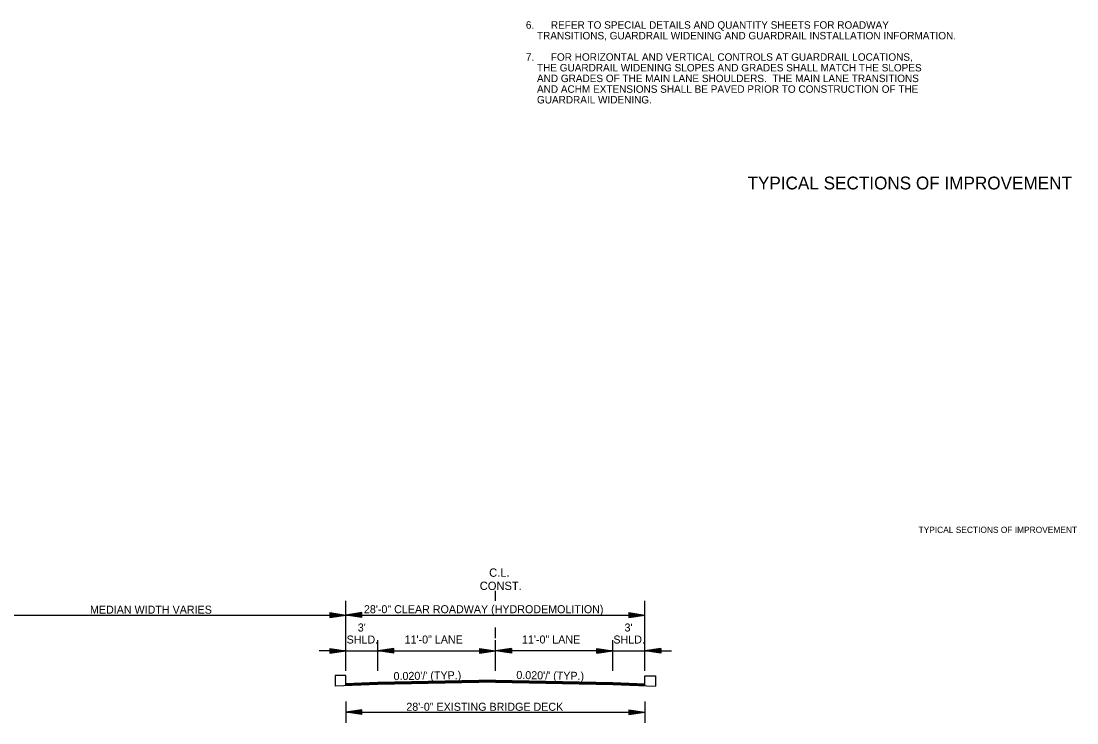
# Model space of a CAD drawing. Extents: x 542112 to 1930787, y -1968972 to 596640.
# Drawn here: x 544766 to 545755, y -1960540 to -1959883 of the extents above; entities that cross this region are included whole.
import ezdxf

# ---------------------------------------------------------------- set-up
doc = ezdxf.new("R2010")
doc.units = 0
for name, color, linetype in [('R_Border', 7, 'Continuous'), ('R_Border Notes', 7, 'Continuous'), ('R_Border Prem', 7, 'Continuous'), ('R_Draft', 7, 'Continuous')]:
    doc.layers.add(name, color=color, linetype=linetype)

msp = doc.modelspace()

# ---------------------------------------------------------------- linework, layer by layer
at = {"layer": 'R_Border'}
for p, q in [((545070.27, -1960495.83), (545060.1, -1960495.83)), ((545060.1, -1960495.83), (545060.1, -1960505.84)), ((545070.27, -1960505.44), (545070.27, -1960495.83)), ((545350.27, -1960496.03), (545360.44, -1960496.03)), ((545350.27, -1960505.44), (545350.27, -1960496.03)), ((545360.44, -1960496.03), (545360.44, -1960505.84))]:
    msp.add_line(p, q, dxfattribs=at)
at = {"layer": 'R_Draft'}
for p, q in [((545210.27, -1960425.81), (545210.27, -1960416.51)), ((545070.27, -1960491.59), (545070.27, -1960425.86)), ((545350.27, -1960491.59), (545350.27, -1960425.86)), ((544700.26, -1960439.22), (545070.27, -1960439.22)), ((545055.27, -1960436.97), (545070.27, -1960439.22)), ((545055.27, -1960436.97), (545055.27, -1960441.47)), ((545055.27, -1960437.35), (545067.76, -1960439.22)), ((545055.27, -1960437.73), (545065.18, -1960439.22)), ((545055.27, -1960438.11), (545062.69, -1960439.22)), ((545055.27, -1960438.5), (545060.14, -1960439.22)), ((545055.27, -1960438.87), (545057.64, -1960439.22)), ((545055.27, -1960441.47), (545070.27, -1960439.22)), ((545055.27, -1960439.96), (545060.14, -1960439.22)), ((545055.27, -1960440.72), (545065.18, -1960439.22)), ((545055.27, -1960441.1), (545067.76, -1960439.22)), ((545055.27, -1960440.34), (545062.69, -1960439.22)), ((545055.27, -1960439.58), (545057.64, -1960439.22)), ((545085.27, -1960436.97), (545070.27, -1960439.22)), ((545070.27, -1960439.22), (545350.27, -1960439.22)), ((545085.27, -1960441.47), (545070.27, -1960439.22)), ((545085.27, -1960437.35), (545072.77, -1960439.22)), ((545085.27, -1960441.1), (545072.77, -1960439.22)), ((545085.27, -1960437.73), (545075.35, -1960439.22)), ((545085.27, -1960440.72), (545075.35, -1960439.22)), ((545085.27, -1960438.11), (545077.85, -1960439.22)), ((545085.27, -1960440.34), (545077.85, -1960439.22)), ((545085.27, -1960438.49), (545080.39, -1960439.22)), ((545085.27, -1960439.95), (545080.39, -1960439.22)), ((545085.27, -1960438.87), (545082.9, -1960439.22)), ((545085.27, -1960439.58), (545082.9, -1960439.22)), ((545085.27, -1960441.47), (545085.27, -1960436.97)), ((545335.27, -1960436.97), (545350.27, -1960439.22)), ((545335.27, -1960436.97), (545335.27, -1960441.47)), ((545335.27, -1960437.35), (545347.76, -1960439.22)), ((545335.27, -1960437.73), (545345.18, -1960439.22)), ((545335.27, -1960438.11), (545342.69, -1960439.22)), ((545335.27, -1960438.5), (545340.14, -1960439.22)), ((545335.27, -1960438.87), (545337.64, -1960439.22)), ((545335.27, -1960441.47), (545350.27, -1960439.22)), ((545335.27, -1960439.96), (545340.14, -1960439.22)), ((545335.27, -1960440.72), (545345.18, -1960439.22)), ((545335.27, -1960441.1), (545347.76, -1960439.22)), ((545335.27, -1960440.34), (545342.69, -1960439.22)), ((545335.27, -1960439.58), (545337.64, -1960439.22)), ((545210.27, -1960460.75), (545210.27, -1960450.88)), ((545100.27, -1960491.59), (545100.27, -1960462.87)), ((545210.27, -1960491.42), (545210.27, -1960462.87)), ((545320.27, -1960491.59), (545320.27, -1960462.87)), ((545350.27, -1960491.59), (545350.27, -1960462.87)), ((545070.27, -1960472.76), (545045.27, -1960472.76)), ((545055.27, -1960470.51), (545070.27, -1960472.76)), ((545055.27, -1960470.51), (545055.27, -1960475.01)), ((545055.27, -1960470.89), (545067.76, -1960472.76)), ((545055.27, -1960471.27), (545065.18, -1960472.76)), ((545055.27, -1960471.64), (545062.69, -1960472.76)), ((545055.27, -1960472.03), (545060.14, -1960472.76)), ((545055.27, -1960472.41), (545057.64, -1960472.76)), ((545055.27, -1960475.01), (545070.27, -1960472.76)), ((545055.27, -1960473.5), (545060.14, -1960472.76)), ((545055.27, -1960474.25), (545065.18, -1960472.76)), ((545055.27, -1960474.64), (545067.76, -1960472.76)), ((545055.27, -1960473.88), (545062.69, -1960472.76)), ((545055.27, -1960473.11), (545057.64, -1960472.76)), ((545070.27, -1960472.76), (545100.27, -1960472.76)), ((545115.27, -1960470.51), (545100.27, -1960472.76)), ((545115.27, -1960475.01), (545100.27, -1960472.76)), ((545100.27, -1960472.76), (545210.27, -1960472.76)), ((545115.27, -1960470.89), (545102.77, -1960472.76)), ((545115.27, -1960474.64), (545102.77, -1960472.76)), ((545115.27, -1960471.27), (545105.35, -1960472.76)), ((545115.27, -1960474.25), (545105.35, -1960472.76)), ((545115.27, -1960471.64), (545107.85, -1960472.76)), ((545115.27, -1960473.88), (545107.85, -1960472.76)), ((545115.27, -1960472.03), (545110.39, -1960472.76)), ((545115.27, -1960473.49), (545110.39, -1960472.76)), ((545115.27, -1960472.41), (545112.9, -1960472.76)), ((545115.27, -1960473.11), (545112.9, -1960472.76)), ((545115.27, -1960475.01), (545115.27, -1960470.51)), ((545195.27, -1960470.51), (545210.27, -1960472.76)), ((545195.27, -1960470.51), (545195.27, -1960475.01)), ((545195.27, -1960470.89), (545207.76, -1960472.76)), ((545195.27, -1960471.27), (545205.18, -1960472.76)), ((545195.27, -1960471.64), (545202.69, -1960472.76)), ((545195.27, -1960472.03), (545200.14, -1960472.76)), ((545195.27, -1960472.41), (545197.64, -1960472.76)), ((545195.27, -1960475.01), (545210.27, -1960472.76)), ((545195.27, -1960473.5), (545200.14, -1960472.76)), ((545195.27, -1960474.25), (545205.18, -1960472.76)), ((545195.27, -1960474.64), (545207.76, -1960472.76)), ((545195.27, -1960473.88), (545202.69, -1960472.76)), ((545195.27, -1960473.11), (545197.64, -1960472.76)), ((545225.27, -1960470.51), (545210.27, -1960472.76)), ((545320.27, -1960472.76), (545210.27, -1960472.76)), ((545225.27, -1960475.01), (545210.27, -1960472.76)), ((545225.27, -1960470.89), (545212.77, -1960472.76)), ((545225.27, -1960474.64), (545212.77, -1960472.76)), ((545225.27, -1960471.27), (545215.35, -1960472.76)), ((545225.27, -1960474.25), (545215.35, -1960472.76)), ((545225.27, -1960471.64), (545217.85, -1960472.76)), ((545225.27, -1960473.88), (545217.85, -1960472.76)), ((545225.27, -1960472.03), (545220.39, -1960472.76)), ((545225.27, -1960473.5), (545220.39, -1960472.76)), ((545225.27, -1960472.41), (545222.9, -1960472.76)), ((545225.27, -1960473.11), (545222.9, -1960472.76)), ((545225.27, -1960470.51), (545225.27, -1960475.01)), ((545305.27, -1960470.51), (545320.27, -1960472.76)), ((545305.27, -1960475.01), (545305.27, -1960470.51)), ((545305.27, -1960470.89), (545317.76, -1960472.76)), ((545305.27, -1960471.27), (545315.18, -1960472.76)), ((545305.27, -1960471.64), (545312.69, -1960472.76)), ((545305.27, -1960472.03), (545310.14, -1960472.76)), ((545305.27, -1960472.41), (545307.64, -1960472.76)), ((545305.27, -1960475.01), (545320.27, -1960472.76)), ((545305.27, -1960473.49), (545310.14, -1960472.76)), ((545305.27, -1960474.25), (545315.18, -1960472.76)), ((545305.27, -1960474.64), (545317.76, -1960472.76)), ((545305.27, -1960473.88), (545312.69, -1960472.76)), ((545305.27, -1960473.11), (545307.64, -1960472.76)), ((545320.27, -1960472.76), (545350.27, -1960472.76)), ((545365.27, -1960470.51), (545350.27, -1960472.76)), ((545365.27, -1960475.01), (545350.27, -1960472.76)), ((545350.27, -1960472.76), (545375.27, -1960472.76)), ((545365.27, -1960470.89), (545352.77, -1960472.76)), ((545365.27, -1960474.64), (545352.77, -1960472.76)), ((545365.27, -1960471.27), (545355.35, -1960472.76)), ((545365.27, -1960474.25), (545355.35, -1960472.76)), ((545365.27, -1960471.64), (545357.85, -1960472.76)), ((545365.27, -1960473.88), (545357.85, -1960472.76)), ((545365.27, -1960472.03), (545360.39, -1960472.76)), ((545365.27, -1960473.5), (545360.39, -1960472.76)), ((545365.27, -1960472.41), (545362.9, -1960472.76)), ((545365.27, -1960473.11), (545362.9, -1960472.76)), ((545365.27, -1960470.51), (545365.27, -1960475.01)), ((545100.27, -1960504.24), (545060.1, -1960505.84)), ((545100.27, -1960502.57), (545070.27, -1960503.77)), ((545100.27, -1960502.87), (545070.27, -1960504.07)), ((545100.27, -1960503.17), (545070.27, -1960504.37)), ((545100.27, -1960503.47), (545070.27, -1960504.67)), ((545100.27, -1960503.77), (545070.27, -1960504.97)), ((545100.27, -1960504.07), (545070.27, -1960505.27)), ((545210.27, -1960500.37), (545100.27, -1960502.57)), ((545210.27, -1960500.67), (545100.27, -1960502.87)), ((545210.28, -1960500.97), (545100.27, -1960503.17)), ((545210.29, -1960501.27), (545100.27, -1960503.47)), ((545210.29, -1960501.57), (545100.27, -1960503.77)), ((545210.3, -1960501.87), (545100.27, -1960504.07)), ((545210.3, -1960502.04), (545100.27, -1960504.24)), ((545210.23, -1960502.04), (545320.27, -1960504.24)), ((545210.24, -1960501.57), (545320.27, -1960503.77)), ((545210.24, -1960501.87), (545320.27, -1960504.07)), ((545210.25, -1960501.27), (545320.27, -1960503.47)), ((545210.26, -1960500.67), (545320.27, -1960502.87)), ((545210.26, -1960500.97), (545320.27, -1960503.17)), ((545210.27, -1960500.37), (545320.27, -1960502.57)), ((545320.27, -1960502.57), (545350.27, -1960503.77)), ((545320.27, -1960502.87), (545350.27, -1960504.07)), ((545320.27, -1960503.17), (545350.27, -1960504.37)), ((545320.27, -1960503.47), (545350.27, -1960504.67)), ((545320.27, -1960503.77), (545350.27, -1960504.97)), ((545320.27, -1960504.07), (545350.27, -1960505.27)), ((545320.27, -1960504.24), (545360.44, -1960505.84)), ((545070.27, -1960520.23), (545070.27, -1960540.23)), ((545350.27, -1960520.23), (545350.27, -1960540.23)), ((545085.27, -1960527.98), (545070.27, -1960530.23)), ((545070.27, -1960530.23), (545350.27, -1960530.23)), ((545085.27, -1960532.48), (545070.27, -1960530.23)), ((545085.27, -1960528.35), (545072.77, -1960530.23)), ((545085.27, -1960532.1), (545072.77, -1960530.23)), ((545085.27, -1960528.73), (545075.35, -1960530.23)), ((545085.27, -1960531.72), (545075.35, -1960530.23)), ((545085.27, -1960529.11), (545077.85, -1960530.23)), ((545085.27, -1960531.34), (545077.85, -1960530.23)), ((545085.27, -1960529.49), (545080.39, -1960530.23)), ((545085.27, -1960530.95), (545080.39, -1960530.23)), ((545085.27, -1960529.87), (545082.9, -1960530.23)), ((545085.27, -1960530.58), (545082.9, -1960530.23)), ((545085.27, -1960532.48), (545085.27, -1960527.98)), ((545335.27, -1960527.98), (545350.27, -1960530.23)), ((545335.27, -1960527.98), (545335.27, -1960532.48)), ((545335.27, -1960528.35), (545347.76, -1960530.23)), ((545335.27, -1960528.73), (545345.18, -1960530.23)), ((545335.27, -1960529.11), (545342.69, -1960530.23)), ((545335.27, -1960529.5), (545340.14, -1960530.23)), ((545335.27, -1960529.87), (545337.64, -1960530.23)), ((545335.27, -1960532.48), (545350.27, -1960530.23)), ((545335.27, -1960530.96), (545340.14, -1960530.23)), ((545335.27, -1960531.72), (545345.18, -1960530.23)), ((545335.27, -1960532.1), (545347.76, -1960530.23)), ((545335.27, -1960531.34), (545342.69, -1960530.23)), ((545335.27, -1960530.58), (545337.64, -1960530.23))]:
    msp.add_line(p, q, dxfattribs=at)

# ---------------------------------------------------------------- texts
at = {"layer": 'R_Border'}
msp.add_text('TYPICAL SECTIONS OF IMPROVEMENT', height=12, rotation=360, dxfattribs=at).set_placement((545446.5, -1960040.69))
at = {"layer": 'R_Border Notes'}
for s, p in [('6.      REFER TO SPECIAL DETAILS AND QUANTITY SHEETS FOR ROADWAY', (545238.85, -1959890.18)), ('    TRANSITIONS, GUARDRAIL WIDENING AND GUARDRAIL INSTALLATION INFORMATION.', (545238.85, -1959900.18)), ('7.      FOR HORIZONTAL AND VERTICAL CONTROLS AT GUARDRAIL LOCATIONS,', (545238.85, -1959920.18)), ('    THE GUARDRAIL WIDENING SLOPES AND GRADES SHALL MATCH THE SLOPES', (545238.85, -1959930.18)), ('    AND GRADES OF THE MAIN LANE SHOULDERS.  THE MAIN LANE TRANSITIONS', (545238.85, -1959940.18)), ('    AND ACHM EXTENSIONS SHALL BE PAVED PRIOR TO CONSTRUCTION OF THE', (545238.85, -1959950.18)), ('    GUARDRAIL WIDENING.', (545238.85, -1959960.18))]:
    msp.add_text(s, height=7, dxfattribs=at).set_placement(p)
at = {"layer": 'R_Border Prem'}
msp.add_text('TYPICAL SECTIONS OF IMPROVEMENT', height=5.862, rotation=360, dxfattribs=at).set_placement((545606.81, -1960362.37))
at = {"layer": 'R_Draft'}
for s, height, p in [('C.L.', 7.8, (545204.42, -1960403.41)), ('CONST.', 7.8, (545195.64, -1960415.78)), ('MEDIAN WIDTH VARIES', 7.5, (544830.38, -1960437.95)), ('28\'-0" CLEAR ROADWAY (HYDRODEMOLITION)', 7.5, (545087.08, -1960437.55)), ("3' ", 7.5, (545081.31, -1960454.67)), ("3' ", 7.5, (545331.31, -1960454.67)), ('SHLD.', 7.5, (545070.86, -1960465.92)), ('11\'-0" LANE', 7.5, (545125.21, -1960465.9)), ('11\'-0" LANE', 7.5, (545235.21, -1960465.9)), ('SHLD.', 7.5, (545320.86, -1960465.92)), ('28\'-0" EXISTING BRIDGE DECK', 7.5, (545126.82, -1960528.9))]:
    msp.add_text(s, height=height, dxfattribs=at).set_placement(p)
for rotation, p in [(0.87191, (545114.89, -1960500.22)), (359.12809, (545229.87, -1960499.09))]:
    msp.add_text("0.020'/' (TYP.)", height=7.5, rotation=rotation, dxfattribs=at).set_placement(p)

doc.saveas('drawing.dxf')
